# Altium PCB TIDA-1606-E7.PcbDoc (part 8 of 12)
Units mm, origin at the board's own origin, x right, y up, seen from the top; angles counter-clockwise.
Board outline 270 x 345 mm, 4 copper layers (Top Layer, Signal Layer 1, Signal Layer 2, Bottom Layer), stack 2.326 mm thick; 1282 components, 576 nets, 3628 pads, 4132 vias.
Unrouted connection lines stored in the file: 1719.
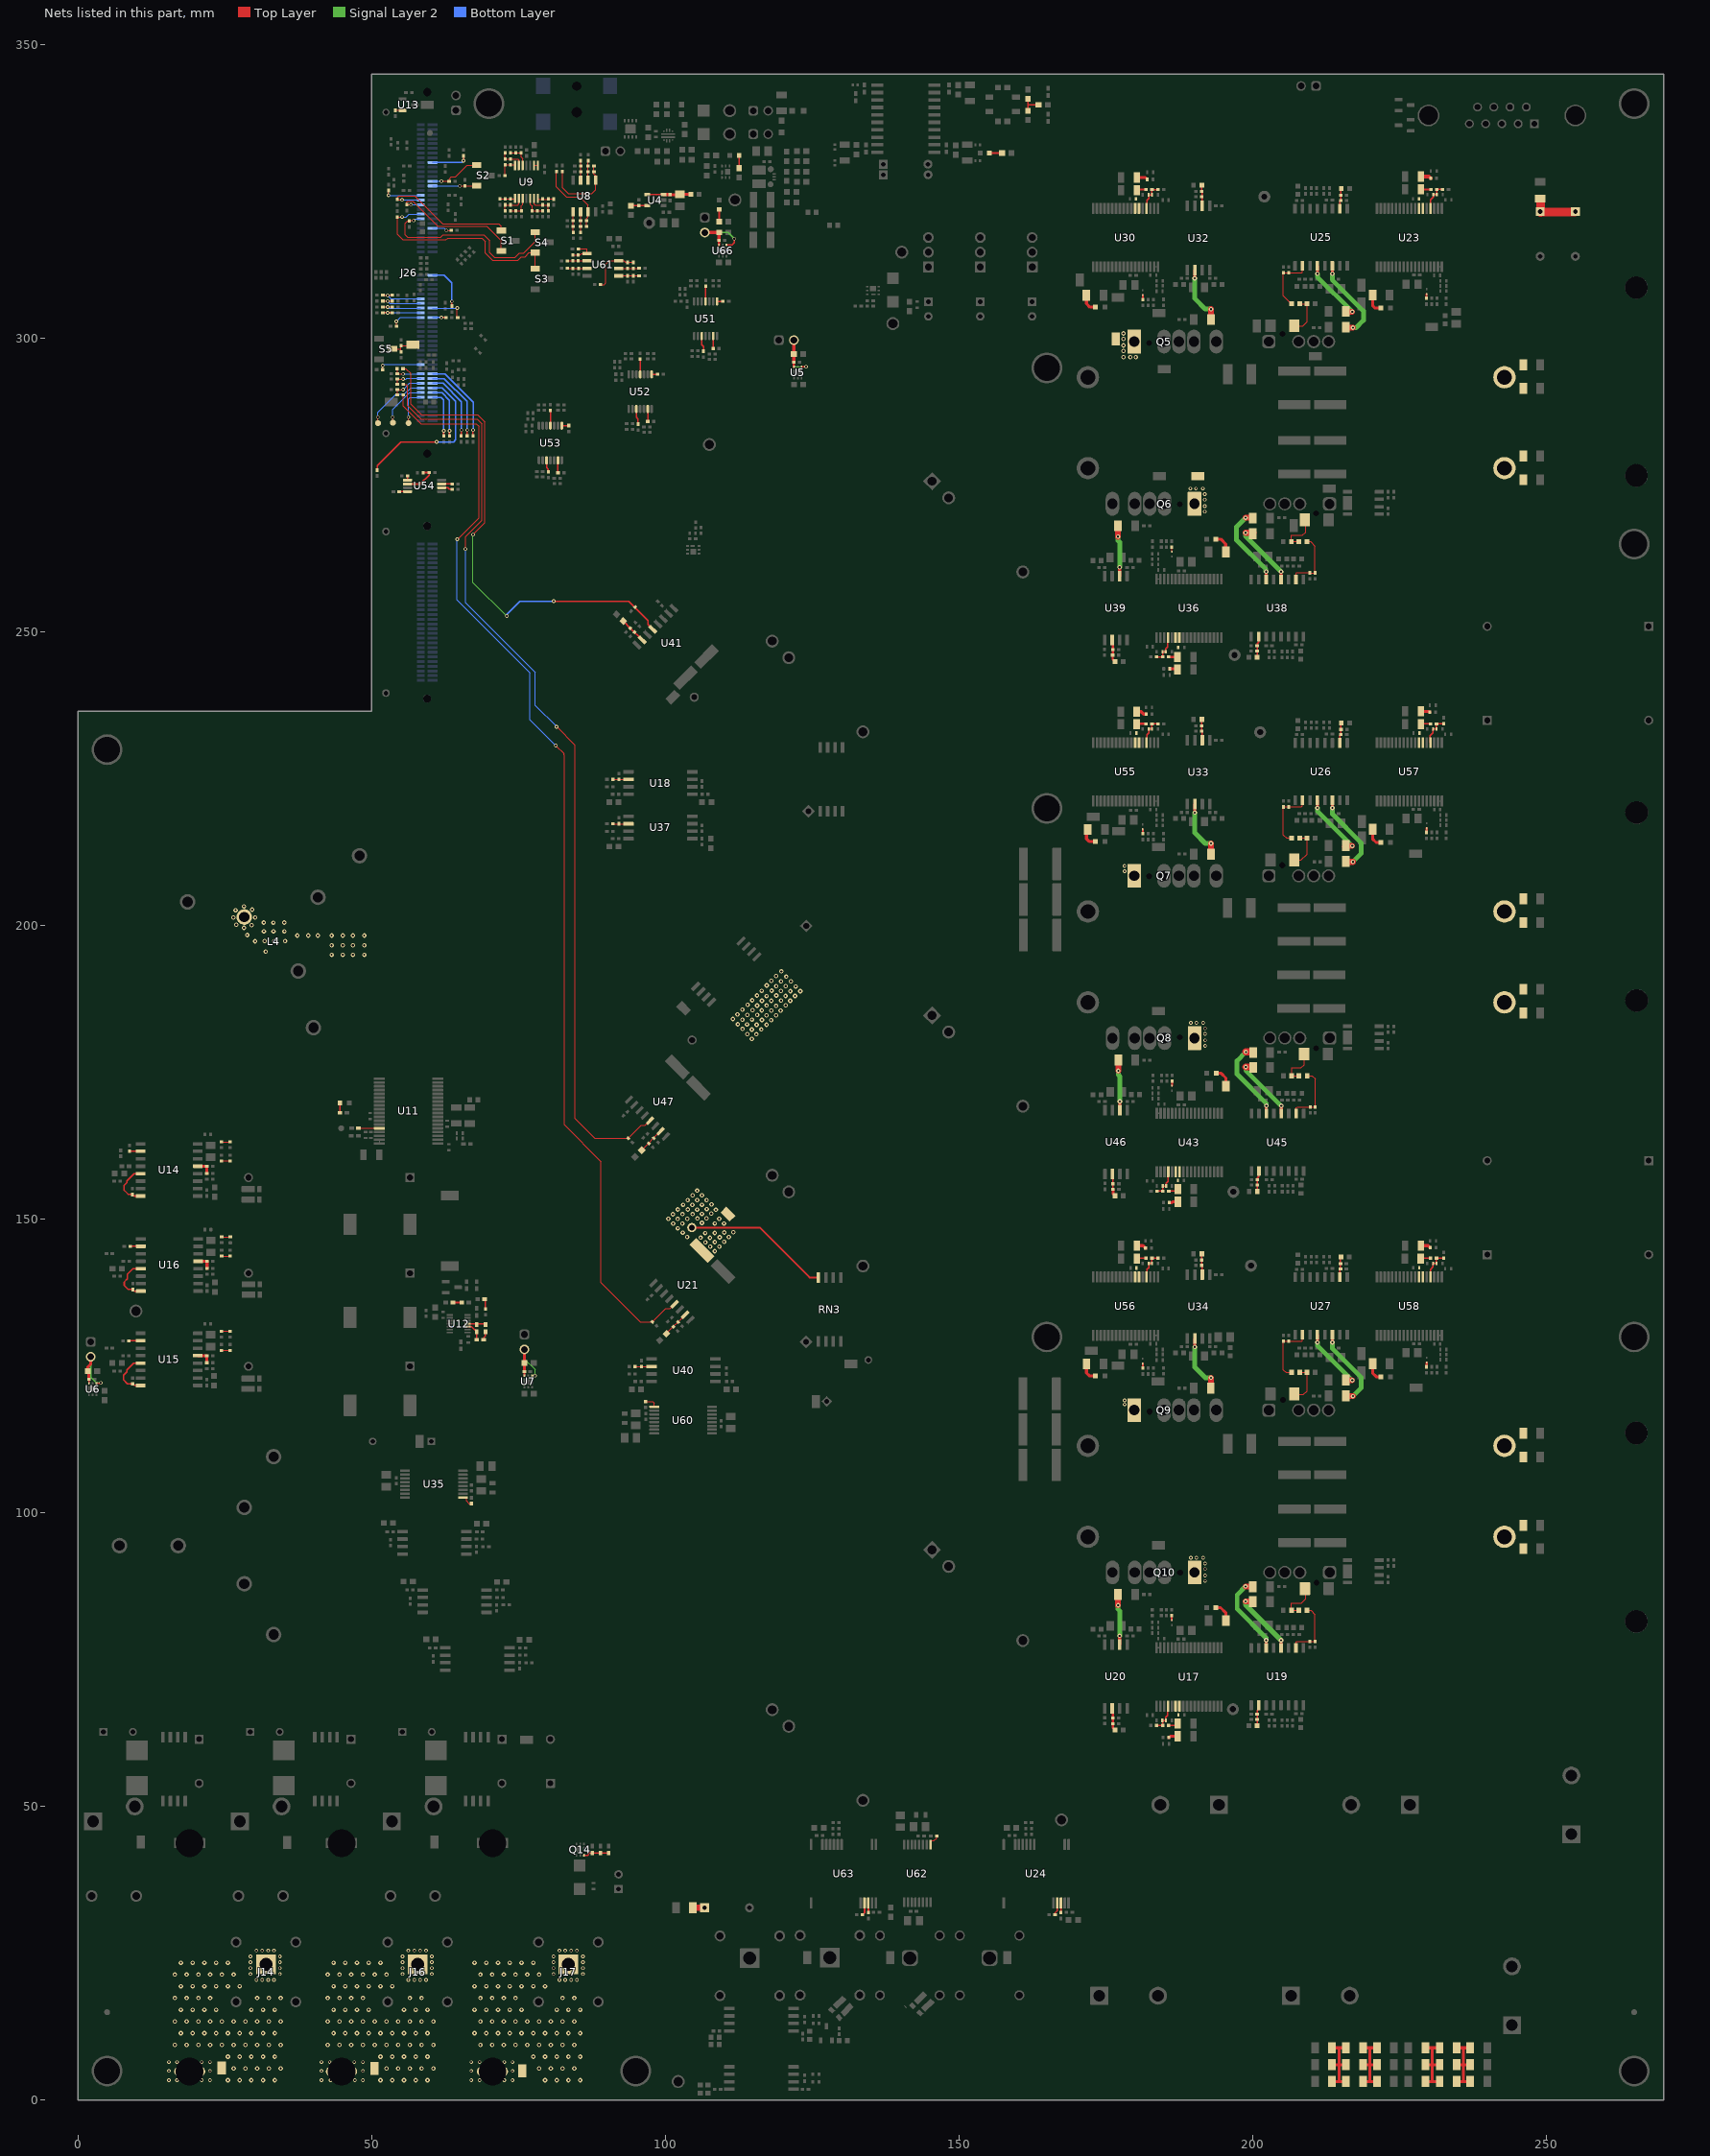
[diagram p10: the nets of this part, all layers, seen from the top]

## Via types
v1: diameter 0.762, hole 0.356, Top Layer to Bottom Layer, tented both sides, 2905 vias
v2: diameter 0.61, hole 0.356, Top Layer to Bottom Layer, tented both sides, 1212 vias
v3: diameter 0.864, hole 0.406, Top Layer to Bottom Layer, tented both sides, 15 vias

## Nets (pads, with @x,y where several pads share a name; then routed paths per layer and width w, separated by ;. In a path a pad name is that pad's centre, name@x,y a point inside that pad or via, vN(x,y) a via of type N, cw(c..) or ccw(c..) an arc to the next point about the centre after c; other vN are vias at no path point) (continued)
I_SN_L3-: C70.2 L4.AIII RN3.4 TP37.1 U21.2 | length 25.1
  Top Layer w0.305: C70.2@104.548,148.612 116.088,148.612 124.6,140.1 RN3.4@126.1,140.1
  other v1: 108.455,144.596 107.684,145.358 109.231,145.376 106.861,146.096 108.46,146.139 110.055,146.196 107.637,146.876 106.055,146.896 109.284,146.958 103.768,146.996 110.855,147.01 106.831,147.676 108.461,147.696 102.996,147.758 110.084,147.773 111.618,147.81 102.173,148.496 102.95,149.276 101.368,149.296 108.455,149.31 110.023,149.31 106.268,149.396 102.144,150.076 100.568,150.096 103.773,150.096 109.218,150.11 105.496,150.158 107.044,150.176 101.344,150.876 102.968,150.896 104.673,150.896 106.273,150.939 107.868,150.996 108.642,151.635 105.45,151.676 102.168,151.696 103.868,151.696 107.096,151.758 104.644,152.476 103.068,152.496 106.273,152.496 107.896,152.558 103.844,153.276 105.468,153.296 107.073,153.296 104.668,154.096 106.268,154.096 105.468,154.896 114.783,180.752 113.983,181.552 115.559,181.533 114.759,182.333 116.383,182.352 113.186,182.43 115.583,183.152 117.283,183.152 113.962,183.211 112.386,183.23 118.059,183.933 116.483,183.952 113.162,184.011 114.786,184.03 111.553,184.13 117.259,184.733 118.883,184.752 113.986,184.83 115.686,184.83 112.329,184.911 118.083,185.552 119.683,185.552 116.462,185.611 114.886,185.63 113.153,185.73 118.883,186.352 115.662,186.411 117.286,186.43 120.532,186.461 114.053,186.53 116.486,187.23 118.086,187.23 121.308,187.241 119.732,187.261 114.829,187.311 117.286,188.03 120.508,188.041 122.132,188.061 115.653,188.13 118.935,188.139 121.332,188.861 123.032,188.861 116.453,188.93 118.135,188.939 119.711,188.919 122.232,189.661 118.911,189.719 120.535,189.739 117.302,189.839 119.735,190.539 121.435,190.539 118.078,190.619 120.635,191.339 118.902,191.439 119.802,192.239 43.221,195.054 45.131,195.054 46.851,195.054 48.782,195.054 32,195.605 43.221,196.657 45.131,196.657 46.851,196.657 48.782,196.657 30.2,197.356 33.444,197.401 31.813,197.409 35.299,197.409 37.385,198.342 39.241,198.342 40.872,198.342 43.221,198.342 45.131,198.342 46.851,198.342 48.782,198.342 28.845,198.422 33.331,199.052 31.7,199.06 35.186,199.06 28.303,199.656 29.6,200.1 27,200.186 31.669,200.54 33.3,200.532 35.155,200.54 26.503,201.4 30.2,201.4 26.881,202.65 29.677,202.761 28.303,203.3
ID_A: J26.53 R436.1 R441.2 | length 7.5
  Top Layer w0.203: R436.1@51.943,307.385 R441.2@53.524,307.385
  Bottom Layer w0.203: v2(52.753,307.368) 53.336,306.785 J26.53@58.402,306.785
ID_B: J26.51 R438.1 R442.2 | length 7.6
  Top Layer w0.203: R438.1@51.943,306.385 v2(52.753,306.385) R442.2@53.524,306.385
  Bottom Layer w0.203: v2@52.517,306.385 52.532,306.4 v2@52.649,306.282 ; v2(52.753,306.385) 53.153,305.985 J26.51@58.402,305.985
ID_C: J26.49 R439.1 R443.2 | length 7.6
  Top Layer w0.203: R439.1@51.943,305.385 52.738,305.385 v2(52.753,305.371) 53.509,305.371 R443.2@53.524,305.385
  Bottom Layer w0.203: v2@52.642,305.26 52.717,305.185 v2@52.938,305.185 ; v2(52.753,305.371) v2@52.938,305.185 ; J26.49@58.402,305.185 v2@52.938,305.185
ID_D: J26.47 R440.1 R444.2 | length 7.2
  Top Layer w0.229: R440.1@51.943,304.385 v2(52.753,304.385) R444.2@53.524,304.385
  Bottom Layer w0.203: v2(52.753,304.385) J26.47@58.402,304.385
IN+_BOT_L1: C186.1 R196.1 R197.2 U25.10 | length 3.5
  Top Layer w0.229: U25.10@214.88,322.108 214.88,323.362 C186.1@215.029,323.511 R197.2@215.029,324.397 215.029,325.418 R196.1@215.129,325.518
IN+_BOT_L2: C199.1 R210.1 R212.2 U26.10 | length 3.5
  Top Layer w0.229: U26.10@214.882,231.14 214.882,232.367 C199.1@215.058,232.542 R210.1@215.058,234.477
  Top Layer w0.5: R210.1@215.058,234.477 R210.1@215.131,234.55
IN+_BOT_L3: C212.1 R211.1 R227.2 U27.10 | length 3.5
  Top Layer w0.229: U27.10@214.882,140.144 214.882,141.434 C212.1@214.995,141.547 R227.2@214.995,142.433 214.995,143.5 R211.1@215.095,143.6
IN+_TOP_L1: C290.1 R246.1 R288.2 U38.10 | length 3.6
  Top Layer w0.229: R246.1@200.698,245.739 200.798,245.839 R288.2@200.798,246.798 C290.1@200.798,247.719 200.798,248.067 201.068,248.337 U38.10@201.068,249.222
IN+_TOP_L2: C333.1 R264.1 R327.2 U45.10 | length 3.6
  Top Layer w0.229: R264.1@200.839,154.773 R327.2@200.839,155.832 C333.1@200.839,156.753 200.839,157.055 201.109,157.325 U45.10@201.109,158.256
IN+_TOP_L3: C146.1 R157.1 R158.2 U19.10 | length 3.6
  Top Layer w0.254: R157.1@200.8,63.778 R158.2@200.8,64.836 C146.1@200.8,65.758 200.8,66.358 201.07,66.628 U19.10@201.07,67.261
L1_MID_DRAIN: Q5.1 Q6.1 TP30.1 TP31.1
  other v1: 178.049,296.822 179.206,296.822 180.147,296.822 178.049,297.877 178.049,298.818 178.043,299.917 178.043,300.858
  other v2: 191.882,270.521 191.882,271.462 191.876,272.561 191.876,273.502 189.454,274.458 190.395,274.458 191.552,274.458
L2_MID_DRAIN: Q7.1 Q8.1
  other v2: 191.947,179.555 191.947,180.496 191.94,181.595 191.94,182.536 189.519,183.492 190.46,183.492 191.616,183.492 178.251,209.289 178.227,210.173
L3_MID_DRAIN: Q9.1 Q10.1
  other v2: 191.933,88.439 191.933,89.38 191.926,90.479 191.926,91.42 189.505,92.375 190.446,92.375 191.602,92.375 178.251,118.506 178.251,119.167
LMK_1G: R461.1 U54.2 | length 1.9
  Top Layer w0.229: U54.2@61.951,274.578 63.025,274.578 63.254,274.348 R461.1@63.737,274.348
LMK_VDD: C393.2 R287.2 U54.6 | length 5.7
  Top Layer w0.305: U54.6@56.151,275.228 58.317,275.228 59.837,276.748 C393.2@59.837,277.148 R287.2@58.837,277.148
LO_MAG_VIN_L1: C172.1 C173.1 C174.1 FB10.2 R188.2 U23.6 U23.7 | length 3.6
  Top Layer w0.305: C172.1@228.732,325.054 229.083,325.405 R188.2@230.388,325.405
  Top Layer w0.6: C173.1@228.691,327.585 230.097,327.585 FB10.2@230.378,327.304
LO_MAG_VIN_L2: C413.1 C414.1 C415.1 FB11.2 R529.2 U57.6 U57.7 | length 3.4
  Top Layer w0.229: C414.1@228.675,234.074 229.001,234.4 R529.2@230.34,234.4
  Top Layer w0.5: C413.1@228.684,236.529 230.06,236.529 FB11.2@230.216,236.372
LO_MAG_VIN_L3: C421.1 C422.1 C423.1 FB12.2 R537.2 U58.6 U58.7 | length 3.5
  Top Layer w0.229: C421.1@228.675,143.078 229.001,143.405 R537.2@230.34,143.405
  Top Layer w0.5: C422.1@228.683,145.529 229.933,145.529 FB12.2@230.257,145.205
MCU_REF1: J4.1 J5.1 L9.2 | length 8
  Top Layer w1.5: L9.2@249.05,323.655 249.05,321.47 249.1,321.52 J4.1@254.868,321.52
MCU_REF2: J6.1 L6.2 | length 2
  Top Layer w1: L6.2@104.733,32.8 106.726,32.8 J6.1@106.738,32.788
MID_MAG_EN_L2: C402.1 R280.1 R342.2 R361.2 U55.4 | length 4.9
  Top Layer w0.229: U55.4@181.98,231.197 182.041,231.258 182.041,232.542 182.346,232.847 C402.1@182.346,233.5 R342.2@182.901,233.5 182.901,234.396 R280.1@182.904,234.396 ; R280.1@182.899,234.4 R361.2@183.924,234.4
MID_MAG_EN_L3: C410.1 R363.2 R509.1 R512.2 U56.4 | length 4.9
  Top Layer w0.229: U56.4@181.98,140.201 182.041,140.262 182.041,141.484 182.346,141.789 C410.1@182.346,142.505 182.896,142.505 R512.2@182.901,142.5 182.901,143.403 R509.1@182.899,143.405 R363.2@183.924,143.405
MID_MAG_VIN_L1: C232.1 C233.1 C234.1 FB13.2 R250.2 U30.6 U30.7 | length 3.5
  Top Layer w0.305: C232.1@180.389,325.042 180.715,325.368 R250.2@181.897,325.368
  Top Layer w0.5: C233.1@180.344,327.406 181.792,327.406 FB13.2@182.098,327.1
MID_MAG_VIN_L2: C397.1 C398.1 C399.1 FB14.2 R280.2 U55.6 U55.7 | length 3.4
  Top Layer w0.4: C397.1@180.391,234.074 180.717,234.4 R280.2@181.899,234.4
  Top Layer w0.5: C398.1@180.306,236.451 181.071,236.451 181.479,236.042 FB14.2@181.904,236.042
MID_MAG_VIN_L3: C405.1 C406.1 C407.1 FB15.2 R509.2 U56.6 U56.7 | length 3.3
  Top Layer w0.229: C405.1@180.391,143.078 180.717,143.405 R509.2@181.899,143.405
  Top Layer w0.5: C406.1@180.332,145.529 181.378,145.529 FB15.2@181.797,145.11
MP1: MP1.1 R117.2 R120.2
MP2: MP2.2 R118.2 R121.2
MP3: MP3.1 R119.2 R122.2
MP4: MP4.2 R123.2 R126.2
MP5: MP5.2 R124.2 R127.2
MP6: MP6.1 R125.2 R128.2
NetC15_1: C15.1 C16.1 R35.1 U4.3 U4.4 | length 7.5
  Top Layer w0.305: U4.4@96.966,324.52 U4.3@99.716,324.52 ; C15.1@100.825,324.52 C15.1@100.845,324.5 ; C16.1@102.482,324.5 C16.1@102.54,324.558
  Top Layer w0.508: U4.3@99.716,324.52 C15.1@100.825,324.52 ; C15.1@100.845,324.5 C16.1@102.482,324.5 ; C16.1@102.54,324.558 R35.1@104.39,324.558
NetC17_1: C17.1 C18.1 J10.2 U5.4 U5.6 | length 11.7
  Top Layer w0.254: U5.4@123.238,295.193 v2(123.993,295.193)
  Top Layer w0.381: C18.1@121.92,295.977 121.938,295.959 U5.6@121.938,295.193
  Top Layer w0.508: C18.1@121.92,295.977 C17.1@121.92,297.377 J10.2@121.92,299.72
  Signal Layer 2 w0.203: J10.2@121.92,299.72 121.92,295.518 122.245,295.193 v2(123.993,295.193)
NetC22_1: C22.1 C23.1 J11.2 U6.4 U6.6 | length 11.2
  Top Layer w0.254: U6.6@1.9,122.087 C23.1@1.9,122.8 ; U6.4@3.2,122.087 3.866,122.087 v2(3.933,122.154)
  Top Layer w0.508: C23.1@1.9,122.8 1.9,123.961 C22.1@1.7,124.161 1.7,124.873 2.2,125.373 J11.2@2.2,126.6
  Signal Layer 2 w0.254: J11.2@2.2,126.6 2.2,123.133 3.178,122.154 v2(3.933,122.154)
NetC25_1: C25.1 C26.1 J12.2 U7.4 U7.6 | length 10.3
  Top Layer w0.203: U7.4@77.34,123.376 v2(77.856,123.376)
  Top Layer w0.381: U7.6@76.04,123.376 C26.1@76.04,124.108
  Top Layer w0.508: C26.1@76.04,124.108 C25.1@76.04,125.532 J12.2@76.04,127.872
  Signal Layer 2 w0.203: J12.2@76.04,127.872 76.04,126.268 77.856,124.452 v2(77.856,123.376)
NetC32_2: C32.2 R19.1 R22.1 U61.3 | length 3.3
  Top Layer w0.203: R22.1@83.37,311.962 R19.1@84.27,311.962 84.278,311.954 U61.3@86.702,311.954
NetC35_2: C35.2 U24.4 | length 1.6
  Top Layer w0.254: C35.2@167.401,31.956 U24.4@167.401,33.6
NetC62_1: C62.1 R65.1 U18.6 | length 2.6
  Top Layer w0.203: R65.1@91.1,224.939 C62.1@92.12,224.939 U18.6@93.75,224.939
NetC88_1: C88.1 R66.2 | length 1.6
  Top Layer w0.203: C88.1@69.275,136.432 C88.1@69.418,136.289
  Top Layer w0.254: R66.2@69.418,134.863 C88.1@69.418,136.289
NetC91_1: C91.1 R67.1 | length 1.5
  Top Layer w0.381: R67.1@63.849,135.846 C91.1@65.381,135.846
NetC98_1: C98.1 Q14.3 R113.2 R115.2 | length 4.4
  Top Layer w0.229: Q14.3@86.202,41.725 86.766,41.725 87.141,42.1 C98.1@87.627,42.1 R115.2@89.014,42.1 R113.2@90.4,42.1
NetC99_1: C99.1 R72.2 U12.10 | length 3.3
  Top Layer w0.254: U12.10@66.365,131.738 67.063,131.738 C99.1@67.913,130.888 R72.2@67.913,129.515
NetC99_2: C99.2 C101.2 U12.11 | length 3.1
  Top Layer w0.254: U12.11@66.365,132.238 69.268,132.238 C101.2@69.418,132.088
NetC100_2: C100.2 R306.1 R309.1 U9.5 | length 4.1
  Top Layer w0.203: R309.1@73.674,331.6 73.679,331.605 R306.1@74.586,331.605 C100.2@75.51,331.605 ; C100.2@75.535,331.605 75.535,330.892 75.752,330.675 U9.5@75.752,329.468
NetC101_1: C101.1 R72.1 | length 1.5
  Top Layer w0.254: R72.1@69.113,129.515 69.113,129.868 69.418,130.173 C101.1@69.418,130.888
NetC107_2: C107.2 U14.13 U14.16 | length 7.8
  Top Layer w0.254: U14.16@10.691,153.98 9.59,153.98 C107.2@9.331,154.239 9.278,154.292 8.573,154.292 7.9,154.965 7.9,155.809 8.373,156.282 8.373,156.573 9.59,157.79 U14.13@10.691,157.79
NetC109_1: C109.1 C111.1 U14.5 | length 2.7
  Top Layer w0.5: U14.5@20.441,159.06 C111.1@21.965,159.06 C109.1@21.965,157.856
NetC116_2: C116.2 U15.13 U15.16 | length 8.1
  Top Layer w0.254: U15.16@10.691,121.722 9.612,121.722 C116.2@9.342,121.992 8.462,121.992 7.772,122.682 7.772,123.469 8.354,124.051 8.354,124.384 9.502,125.532 U15.13@10.691,125.532
NetC118_1: C118.1 C120.1 U15.5 | length 2.7
  Top Layer w0.5: U15.5@20.441,126.802 C120.1@21.965,126.802 C118.1@21.965,125.598
NetC125_2: C125.2 U16.13 U16.16 | length 8
  Top Layer w0.254: U16.16@10.733,137.795 9.633,137.795 C125.2@9.363,138.065 8.599,138.065 7.911,138.753 7.911,139.35 8.454,139.893 8.454,140.671 9.388,141.605 U16.13@10.733,141.605
NetC127_1: C127.1 C129.1 U16.5 | length 2.7
  Top Layer w0.5: U16.5@20.483,142.875 C129.1@22.007,142.875 C127.1@22.007,141.671
NetC132_1: C132.1 C133.1 C134.1 FB21.2 R153.2 U17.6 U17.7 | length 3.2
  Top Layer w0.229: R153.2@185.719,63.836 186.955,63.836 C133.1@187.268,64.149
  Top Layer w0.5: FB21.2@185.797,61.788 186.008,62 C132.1@187.267,62
NetC143_1: C143.1 R152.2 R153.1 R364.2 U17.4 | length 5
  Top Layer w0.229: R364.2@183.703,63.836 R153.1@184.719,63.836 184.719,64.685 C143.1@185.26,64.685 185.26,65.205 185.57,65.515 185.57,67.068 U17.4@185.626,67.124
NetC156_1: C156.1 R166.1 R169.2 U19.2 | length 10.6
  Top Layer w0.203: U19.2@207.42,77.011 207.42,78.067 207.514,78.161 209.773,78.161 C156.1@209.8,78.134 R169.2@210.666,78.134 210.666,82.746 209.959,83.452 R166.1@209.284,83.452
NetC162_1: C162.1 R174.1 R175.1 U20.2 | length 3.9
  Top Layer w0.4: U20.2@176.121,66.707 176.221,66.607 C162.1@176.221,65.073 R175.1@176.221,64.145 176.221,63.421 R174.1@176.595,63.047
NetC167_2: C167.2 R311.1 R313.2 U9.6 | length 4.4
  Top Layer w0.203: R311.1@72.761,331.6 72.776,331.585 72.776,330.56 72.784,330.568 C167.2@73.676,330.568 73.676,330.593 74.914,330.593 75.102,330.405 U9.6@75.102,329.468
NetC169_2: C169.2 R345.1 R346.1 U9.10 | length 4.1
  Top Layer w0.203: R346.1@73.674,321.753 R345.1@74.6,321.753 C169.2@75.535,321.753 75.535,322.605 75.752,322.822 U9.10@75.752,323.868
NetC175_1: C175.1 R25.1 R28.1 U61.2 | length 3.3
  Top Layer w0.203: R25.1@83.37,313.226 83.372,313.224 R28.1@84.27,313.224 C175.1@85.226,313.224 U61.2@86.702,313.224
NetC183_1: C183.1 R188.1 R193.2 R446.2 U23.4 | length 5
  Top Layer w0.229: U23.4@230.356,322.214 230.356,323.635 230.81,324.089 C183.1@230.81,324.505 R193.2@231.388,324.505 R188.1@231.388,325.405 R446.2@232.381,325.405
NetC196_1: C196.1 R205.1 R208.2 U25.2 | length 10.2
  Top Layer w0.203: R205.1@206.666,305.914 205.284,307.296 R208.2@205.284,311.208 C196.1@206.152,311.208 208.462,311.208 208.53,311.276 U25.2@208.53,312.358
NetC209_1: C209.1 R220.1 R223.2 U26.2 | length 10.7
  Top Layer w0.203: R220.1@206.668,214.945 205.803,214.945 205.286,215.462 R223.2@205.286,220.24 C209.1@206.154,220.24 208.37,220.24 208.532,220.402 U26.2@208.532,221.39
NetC223_1: C223.1 R234.1 R239.1 U8.3 | length 3.3
  Top Layer w0.203: U8.3@85.617,326.954 85.617,330.278 R239.1@85.625,330.286
NetC228_1: C228.1 R236.1 R245.2 U27.2 | length 10.8
  Top Layer w0.203: R236.1@206.668,123.95 205.714,123.95 205.286,124.378 R245.2@205.286,129.244 C228.1@206.154,129.244 208.437,129.244 208.532,129.34 U27.2@208.532,130.394
NetC230_1: C230.1 R241.1 R244.2 U8.2 | length 3.3
  Top Layer w0.203: U8.2@86.887,326.954 C230.1@86.887,328.43 R244.2@86.887,329.386 86.887,330.284 R241.1@86.889,330.286
NetC243_1: C243.1 R250.1 R255.2 R447.2 U30.4 | length 4.9
  Top Layer w0.229: U30.4@181.978,322.165 182.039,322.226 182.039,323.539 182.344,323.844 C243.1@182.344,324.468 R255.2@182.899,324.468 182.899,325.366 R250.1@182.897,325.368 R447.2@183.922,325.368
NetC249_1: C249.1 R224.1 R261.1 U32.2 | length 3.6
  Top Layer w0.229: R224.1@191.375,326.11 R261.1@191.375,325.039 191.465,324.949 U32.2@191.465,322.568
NetC256_1: C256.1 R226.1 R265.1 U33.2 | length 3.6
  Top Layer w0.229: R226.1@191.377,235.142 R265.1@191.377,234.071 C256.1@191.377,233.174 191.467,233.084 U33.2@191.467,231.6
NetC263_1: C263.1 R242.1 R269.1 U34.2 | length 3.6
  Top Layer w0.229: R242.1@191.377,144.147 C263.1@191.377,143.076 R269.1@191.377,142.178 191.467,142.088 U34.2@191.467,140.605
NetC272_1: C272.1 R270.1 R272.2 U8.5 | length 3.5
  Top Layer w0.203: R272.2@84.347,318.089 R270.1@84.347,319.086 C272.1@84.347,320.059 U8.5@84.347,321.554
NetC275_1: C275.1 R274.2 R276.1 U8.6 | length 3.5
  Top Layer w0.203: R274.2@85.614,318.089 R276.1@85.614,319.086 C275.1@85.614,320.059 85.617,320.062 U8.6@85.617,321.554
NetC276_1: C276.1 C277.1 C278.1 FB22.2 R279.2 U36.6 U36.7 | length 3.1
  Top Layer w0.4: R279.2@185.717,245.798 186.953,245.798 C276.1@187.266,246.111
  Top Layer w0.5: FB22.2@185.903,243.764 187.107,243.764 C277.1@187.248,243.623
NetC287_1: C287.1 R279.1 R282.2 R448.2 U36.4 | length 5
  Top Layer w0.229: R448.2@183.701,245.798 R279.1@184.717,245.798 184.717,246.646 C287.1@185.258,246.646 185.258,247.16 185.568,247.47 185.568,248.643 185.624,248.699 U36.4@185.624,249.085
NetC306_1: C306.1 R260.1 R305.1 U39.2 | length 3.9
  Top Layer w0.4: U39.2@176.119,248.668 176.219,248.568 C306.1@176.219,247.035 R305.1@176.219,246.106 ; R305.1@176.206,246.093 176.206,245.379 R260.1@176.585,245
NetC313_2: C313.2 R348.1 R349.2 U9.9 | length 4.4
  Top Layer w0.203: R348.1@72.761,321.753 72.761,322.742 72.759,322.743 74.919,322.743 75.102,322.927 U9.9@75.102,323.868
NetC314_2: C314.2 R17.2 U4.5 | length 2.8
  Top Layer w0.25: R17.2@94.16,322.62 C314.2@95.532,322.62 U4.5@96.966,322.62
NetC316_2: C316.2 R176.1 R179.1 U9.12 | length 4.1
  Top Layer w0.203: U9.12@77.052,323.868 77.052,322.836 77.362,322.526 C316.2@77.362,321.753 R176.1@78.251,321.753 R179.1@79.187,321.753
NetC319_1: C319.1 C320.1 C321.1 FB23.2 R316.2 U43.6 U43.7 | length 3.2
  Top Layer w0.229: R316.2@185.758,154.832 186.994,154.832 C319.1@187.307,155.145
  Top Layer w0.5: FB23.2@185.828,152.857 186.28,152.857 186.42,152.997 187.308,152.997 C320.1@187.31,153
NetC330_1: C330.1 R316.1 R321.2 R450.2 U43.4 | length 5
  Top Layer w0.229: R450.2@183.742,154.832 R316.1@184.758,154.832 184.758,155.68 C330.1@185.3,155.68 185.3,156.168 185.61,156.478 185.61,158.063 U43.4@185.666,158.119
NetC335_2: C335.2 R181.1 R184.2 U9.13 | length 4.4
  Top Layer w0.203: U9.13@77.702,323.868 77.702,322.885 77.859,322.729 79.187,322.729 79.188,322.73 80.111,322.73 R181.1@80.111,321.753
NetC343_1: C343.1 R335.1 R338.2 U45.2 | length 10.7
  Top Layer w0.203: U45.2@207.459,168.006 207.459,169.032 207.584,169.156 209.815,169.156 C343.1@209.839,169.132 R338.2@210.705,169.132 210.705,173.925 210.18,174.45 R335.1@209.323,174.45
NetC349_1: C349.1 R268.1 R337.1 U46.2 | length 3.9
  Top Layer w0.229: U46.2@176.169,157.71 176.261,157.618 C349.1@176.261,156.069 R337.1@176.261,155.14
  Top Layer w0.5: R337.1@176.261,155.14 176.261,154.4 R268.1@176.627,154.034
NetC351_1: C351.1 R70.1 U37.6 | length 2.7
  Top Layer w0.203: R70.1@91.1,217.374 C351.1@92.12,217.374 U37.6@93.75,217.374
NetC359_1: C359.1 R75.1 U40.6 | length 2.8
  Top Layer w0.203: R75.1@94.889,124.952 C359.1@95.989,124.952 U40.6@97.693,124.952
NetC378_2: C378.2 R385.1 R386.2 | length 3.8
  Top Layer w0.229: R386.2@161.798,338.8 161.798,339.806 ; R385.1@161.798,340.812 161.798,339.806 ; C378.2@163.576,339.8 161.804,339.8 161.798,339.806
NetC385_1: C385.1 R374.1 S5.2 TP9.1 | length 4.6
  Top Layer w0.203: S5.2@53.602,298.237 54.991,298.237 55.019,298.265 ; C385.1@55.019,297.74 55.019,298.265 ; TP9.1@57.067,298.965 56.891,298.789 R374.1@55.019,298.789 55.019,298.265
NetC418_1: C418.1 R351.2 R529.1 R532.2 U57.4 | length 5.3
  Top Layer w0.229: U57.4@230.252,231.14 230.252,232.341 230.762,232.851 C418.1@230.762,233.5 R532.2@231.34,233.5 R529.1@231.34,234.4 R351.2@232.548,234.4
NetC425_1: C425.1 R183.2 R185.1 U21.9 | length 4.6
  Top Layer w0.203: R183.2@100.214,130.543 103.42,133.748 U21.9@103.42,133.776
NetC426_1: C426.1 R353.2 R537.1 R540.2 U58.4 | length 5.2
  Top Layer w0.229: U58.4@230.309,140.201 230.309,141.469 230.762,141.921 C426.1@230.762,142.505 R540.2@231.34,142.505 R537.1@231.34,143.405 R353.2@232.548,143.405
NetC429_1: C429.1 R312.2 R314.1 U41.9 | length 4.6
  Top Layer w0.229: R312.2@92.879,251.9 92.879,251.878 R314.1@94.058,250.7 96.063,248.695 U41.9@96.112,248.695
NetC430_1: C430.1 R344.1 R352.2 U47.9 | length 4.6
  Top Layer w0.203: R352.2@96.028,161.785 96.028,161.812 U47.9@99.234,165.018
NetC444_2: C444.2 R29.1 R32.1 U61.5 | length 3.5
  Top Layer w0.203: U61.5@92.102,310.684 C444.2@93.597,310.684 R29.1@94.57,310.684 95.567,310.684 R32.1@95.57,310.687
NetC452_1: C452.1 C483.1 J31.2 U66.4 U66.6 | length 12.1
  Top Layer w0.254: U66.4@110.467,315.958 111.409,315.958 111.798,316.346 v2(111.798,316.998)
  Top Layer w0.381: U66.6@109.167,315.958 C483.1@109.167,316.7
  Top Layer w0.508: J31.2@106.767,318.06 109.167,318.06 C483.1@109.167,316.7
  Signal Layer 2 w0.254: J31.2@106.767,318.06 110.736,318.06 v2(111.798,316.998)
NetC454_2: C454.2 U63.4 | length 1.6
  Top Layer w0.305: C454.2@134.599,31.956 U63.4@134.599,33.6
NetC455_1: C455.1 R34.1 R37.1 U61.6 | length 3.5
  Top Layer w0.203: U61.6@92.102,311.954 95.562,311.954 R34.1@95.57,311.962
NetD1_1: D1.1 R7.2 | length 2.2
  Top Layer w0.305: R7.2@112.602,329.02 D1.1@112.602,331.17
NetD3_1: D3.1 R15.2 | length 2.1
  Top Layer w0.254: R15.2@109.193,319.902 R15.2@109.209,319.885
  Top Layer w0.305: R15.2@109.193,319.902 D3.1@109.193,321.985
NetD4_1: D4.1 R61.2 | length 1.7
  Top Layer w0.305: R61.2@44.635,168.163 D4.1@44.635,169.816
NetD7_2: D7.2 R149.1 | length 0.8
  Top Layer w0.305: D7.2@186.276,81.754 R149.1@186.276,82.534
NetD8_2: D8.2 R163.1 R166.2 | length 7
  Top Layer w0.203: R166.2@207.884,83.452 R163.1@206.644,83.452 206.644,84.684 208.357,84.684 209.062,85.389 D8.2@209.062,87.21
NetD10_2: D10.2 R202.1 R205.2 | length 7
  Top Layer w0.203: D10.2@206.888,302.157 208.619,302.157 209.306,302.844 R202.1@209.306,305.914 R205.2@208.066,305.914
NetD11_2: D11.2 R217.1 R220.2 | length 6.8
  Top Layer w0.203: D11.2@206.89,211.188 208.266,211.188 209.306,212.228 209.306,214.943 R217.1@209.308,214.945 R220.2@208.068,214.945
NetD12_2: D12.2 R232.1 R236.2 | length 7.1
  Top Layer w0.203: D12.2@206.89,120.193 208.693,120.193 209.308,120.808 R232.1@209.308,123.95 R236.2@208.068,123.95
NetD14_2: D14.2 R277.1 | length 0.8
  Top Layer w0.203: D14.2@186.274,263.718 R277.1@186.274,264.498
NetD15_2: D15.2 R293.1 R296.2 | length 7.1
  Top Layer w0.203: R296.2@207.882,265.416 R293.1@206.642,265.416 206.644,265.418 206.644,266.502 208.527,266.502 209.06,267.036 D15.2@209.06,269.173
NetD16_2: D16.2 R284.1 | length 0.8
  Top Layer w0.35: D16.2@186.316,172.752 R284.1@186.316,173.532
NetD17_2: D17.2 R332.1 R335.2 | length 6.8
  Top Layer w0.203: R335.2@207.923,174.45 R332.1@206.683,174.45 206.683,175.817 208.28,175.817 208.802,176.339 D17.2@208.802,178.151
NetD18_1: D18.1 R382.2 | length 2.1
  Top Layer w0.305: D18.1@155.241,331.605 157.36,331.605 R382.2@157.379,331.585
NetD19_2: D19.2 R186.1 | length 0.7
  Top Layer w0.35: R186.1@229.657,306.873 D19.2@229.657,307.586
  Top Layer w0.4: R186.1@229.657,306.873 R186.1@229.664,306.866
NetD20_2: D20.2 R535.1 | length 0.7
  Top Layer w0.35: R535.1@229.666,215.898 D20.2@229.666,216.611
NetD21_2: D21.2 R557.1 | length 0.7
  Top Layer w0.35: R557.1@229.666,124.902 D21.2@229.666,125.616
NetD22_1: D22.1 R560.2 | length 3.4
  Top Layer w0.5: R560.2@220.448,307.391 220.448,305.625 220.905,305.168 D22.1@221.898,305.168
NetD23_1: D23.1 R561.2 | length 3.3
  Top Layer w0.5: R561.2@220.45,216.423 220.45,214.8 221.05,214.2 D23.1@221.9,214.2
NetD24_1: D24.1 R562.2 | length 3.3
  Top Layer w0.5: R562.2@220.45,125.428 220.45,123.85 221.095,123.205 D24.1@221.9,123.205
NetD25_2: D25.2 R507.1 | length 0.7
  Top Layer w0.35: R507.1@181.328,306.646 D25.2@181.328,307.391
NetD26_2: D26.2 R565.1 | length 0.7
  Top Layer w0.35: R565.1@181.33,215.678 D26.2@181.33,216.423
NetD27_2: D27.2 R567.1 | length 0.7
  Top Layer w0.35: R567.1@181.33,124.682 D27.2@181.33,125.428
NetD28_1: D28.1 R568.2 | length 3.2
  Top Layer w0.5: R568.2@171.748,307.368 171.748,305.937 172.345,305.339 D28.1@173.285,305.339
NetD29_1: D29.1 R569.2 | length 3.3
  Top Layer w0.5: R569.2@171.75,216.4 171.75,214.787 172.166,214.371 D29.1@173.287,214.371
NetD30_1: D30.1 R570.2 | length 3.3
  Top Layer w0.5: R570.2@171.75,125.405 171.75,123.853 172.227,123.376 D30.1@173.287,123.376
NetD31_1: D31.1 R318.2 | length 3.4
  Top Layer w0.5: D31.1@193.8,83.876 193.823,83.9 194.6,83.9 195.45,83.05 R318.2@195.45,81.684
NetD32_1: D32.1 R322.2 | length 3.3
  Top Layer w0.5: D32.1@193.798,265.84 194.605,265.84 195.448,264.998 R322.2@195.448,263.648
NetD33_1: D33.1 R323.2 | length 3.4
  Top Layer w0.5: D33.1@193.839,174.874 194.69,174.874 195.489,174.075 R323.2@195.489,172.682
NetFB1_2: FB1.2 R134.1 | length 1.5
  Top Layer w0.203: R134.1@24.456,159.956 FB1.2@25.912,159.956
NetFB2_2: FB2.2 R136.1 | length 1.5
  Top Layer w0.203: R136.1@24.456,163.213 24.466,163.203 FB2.2@25.927,163.203
NetFB4_2: FB4.2 R139.1 | length 1.5
  Top Layer w0.203: R139.1@24.456,127.698 FB4.2@25.912,127.698
NetFB5_2: FB5.2 R141.1 | length 1.5
  Top Layer w0.203: R141.1@24.456,130.955 25.917,130.955 FB5.2@25.927,130.945
NetFB7_2: FB7.2 R144.1 | length 1.5
  Top Layer w0.203: R144.1@24.498,143.771 FB7.2@25.954,143.771
NetFB8_2: FB8.2 R146.1 | length 1.5
  Top Layer w0.203: R146.1@24.498,147.028 25.959,147.028 FB8.2@25.969,147.018
NetJ26_11: J26.11 TP19.1 | length 6.3
  Top Layer w0.203: v2(56.302,286.618) 56.318,286.603 TP19.1@56.318,285.6
  Bottom Layer w0.203: v2(56.302,286.618) 56.302,289.73 56.558,289.985 J26.11@58.402,289.985
NetJ26_12: J26.12 R481.2 | length 8.2
  Top Layer w0.229: R481.2@62.322,283.42 v2(62.322,284.3)
  Bottom Layer w0.229: J26.12@60.402,289.985 61.886,289.985 62.322,289.55 v2(62.322,284.3)
NetJ26_13: J26.13 TP18.1 | length 8.2
  Top Layer w0.203: TP18.1@53.636,285.662 v2(53.636,286.6)
  Bottom Layer w0.203: v2(53.636,286.6) 53.636,287.933 56.488,290.785 J26.13@58.402,290.785
NetJ26_14: J26.14 R478.2 | length 9.5
  Top Layer w0.229: R478.2@63.302,283.42 v2(63.302,284.3)
  Bottom Layer w0.229: J26.14@60.402,290.785 62.001,290.785 63.302,289.484 v2(63.302,284.3)
NetJ26_15: J26.15 TP16.1 | length 10.8
  Top Layer w0.203: TP16.1@51.102,285.6 v2(51.102,286.6)
  Bottom Layer w0.203: v2(51.102,286.6) 51.102,287.4 54.202,290.5 55.602,290.5 56.688,291.585 J26.15@58.402,291.585
NetJ26_16: J26.16 R477.2 | length 27.3
  Top Layer w0.229: R477.2@51.002,277.6 51.002,278.4 55.002,282.4 v2(61.112,282.4)
  Bottom Layer w0.229: J26.16@60.402,291.585 62.017,291.585 64.304,289.298 64.304,282.744 63.96,282.4 v2(61.112,282.4)
NetJ26_18: J26.18 R475.2 | length 12
  Top Layer w0.229: R475.2@65.28,283.42 65.28,284.378 v2(65.302,284.4)
  Bottom Layer w0.229: J26.18@60.402,292.385 62.167,292.385 65.302,289.25 v2(65.302,284.4)
NetJ26_20: J26.20 R471.2 | length 13.4
  Top Layer w0.229: R471.2@66.28,283.42 66.28,284.378 v2(66.302,284.4)
  Bottom Layer w0.229: J26.20@60.402,293.185 62.393,293.185 66.302,289.276 v2(66.302,284.4)
NetJ26_22: J26.22 R469.2 | length 14.7
  Top Layer w0.229: R469.2@67.28,283.42 67.28,284.368 v2(67.312,284.4)
  Bottom Layer w0.229: J26.22@60.402,293.985 62.502,293.985 67.312,289.175 v2(67.312,284.4)
NetJ26_25: J26.25 R467.1 | length 7.3
  Top Layer w0.203: R467.1@51.902,294.716 v2(51.902,295.385)
  Bottom Layer w0.203: v2(51.902,295.385) 52.102,295.585 J26.25@58.402,295.585
NetJ26_45: J26.45 R449.1 | length 5.2
  Top Layer w0.203: R449.1@54.25,302.1 v2(54.25,302.9)
  Bottom Layer w0.203: v2(54.25,302.9) 54.936,303.585 J26.45@58.402,303.585
NetJ26_46: J26.46 R367.2 | length 2.3
  Top Layer w0.229: v2(61.902,303.585) 62.672,303.585 R367.2@62.686,303.6
  Bottom Layer w0.229: J26.46@60.408,303.592 J26.46@60.402,303.585 v2(61.902,303.585)
NetJ26_50: J26.50 R445.2 | length 5.8
  Top Layer w0.203: R445.2@64.602,303.7 v2(64.602,305.185)
  Top Layer w0.229: R445.2@64.602,303.7 R445.2@64.702,303.6
  Bottom Layer w0.203: J26.50@60.402,305.185 v2(64.602,305.185)
NetJ26_64: J26.64 R355.2 | length 7.8
  Top Layer w0.229: v2(63.686,306.3) 63.686,305.6 R355.2@63.702,305.616
  Bottom Layer w0.229: J26.64@60.402,310.785 62.402,310.785 63.702,309.485 63.702,306.316 v2(63.686,306.3)
NetJ26_76: J26.76 R304.2 | length 3.3
  Top Layer w0.203: v2(62.771,318.4) R304.2@63.568,318.4 ; R304.2@63.599,318.297 R304.2@63.602,318.3
  Bottom Layer w0.203: J26.76@60.402,318.785 62.386,318.785 v2(62.771,318.4)
NetJ26_89: J26.89 R411.1 | length 6.3
  Top Layer w0.203: v2(52.902,324.385) R411.1@52.902,325.204
  Bottom Layer w0.203: v2(52.902,324.385) J26.89@58.402,324.385
NetJ26_104: J26.104 R396.2 | length 6.2
  Top Layer w0.25: v2(65.688,330.286) 65.702,330.3 R396.2@65.702,331.092
  Bottom Layer w0.25: J26.104@60.402,329.985 65.387,329.985 v2(65.688,330.286)
NetR21_1: R21.1 U24.3 | length 2.2
  Top Layer w0.254: R21.1@166.4,31.582 166.4,31.927 166.75,32.278 U24.3@166.75,33.6
NetR23_2: R23.2 U62.1 | length 2.2
  Top Layer w0.203: U62.1@145.227,43.555 145.227,44.2 145.792,44.2 146.242,44.65 R23.2@146.242,45
NetR31_1: R31.1 U63.3 | length 2.2
  Top Layer w0.305: R31.1@133.598,31.582 133.949,31.932 U63.3@133.949,33.6
NetR38_1: R38.1 U11.32 | length 3.5
  Top Layer w0.203: R38.1@47.809,165.521 U11.32@51.343,165.521
NetR41_1: R41.1 R42.1 R43.1 R44.2 R45.2 R46.2 | length 12.9
  Top Layer w0.508: R41.1@213.547,3.192 214.734,3.192 ; R43.1@213.547,6.06 214.734,6.06 ; R42.1@213.547,8.928 214.734,8.928 ; R44.2@215.921,3.192 214.734,3.192 ; R46.2@215.921,6.06 214.734,6.06 ; R45.2@215.921,8.928 214.734,8.928 ; 214.734,3.192 214.734,6.06 ; 214.734,6.06 214.734,8.928
NetR44_1: R44.1 R45.1 R46.1 R47.2 R48.2 R49.2 | length 12.8
  Top Layer w0.508: R44.1@218.821,3.192 219.99,3.192 ; R46.1@218.821,6.06 220.006,6.06 ; R45.1@218.821,8.928 220.006,8.928 ; R47.2@221.19,3.192 219.99,3.192 ; R49.2@221.19,6.06 220.006,6.06 ; R48.2@221.19,8.928 220.006,8.928 ; 219.99,3.192 220.006,3.207 220.006,6.06 ; 220.006,6.06 220.006,8.928
NetR51_1: R51.1 R52.1 R53.1 R54.2 R55.2 R56.2 | length 13.1
  Top Layer w0.508: R51.1@229.442,3.192 230.659,3.192 ; R53.1@229.442,6.06 230.582,6.06 ; R52.1@229.442,8.928 230.582,8.928 ; R54.2@231.876,3.192 230.659,3.192 ; R56.2@231.876,6.06 230.582,6.06 ; R55.2@231.876,8.928 230.582,8.928 ; 230.582,6.06 230.582,8.928 ; 230.582,6.06 230.582,3.269 230.659,3.192
NetR54_1: R54.1 R55.1 R56.1 R57.2 R58.2 R59.2 | length 12.7
  Top Layer w0.508: R54.1@234.776,3.192 235.901,3.192 ; R56.1@234.776,6.06 235.934,6.06 ; R55.1@234.776,8.928 235.934,8.928 ; R57.2@237.092,3.192 235.901,3.192 ; R59.2@237.092,6.06 235.934,6.06 ; R58.2@237.092,8.928 235.934,8.928 ; 235.901,3.192 235.934,3.224 235.934,6.06 ; 235.934,6.06 235.934,8.928
NetR76_2: R76.2 U60.1 | length 2.2
  Top Layer w0.203: R76.2@96.68,119 97.9,119 98.15,118.75 U60.1@98.15,118.1
NetR101_1: R101.1 U51.3 | length 2.7
  Top Layer w0.229: U51.3@106.243,300.431 106.243,298.946 106.546,298.643 R101.1@106.546,297.846
NetR102_1: R102.1 U51.6 | length 2.1
  Top Layer w0.229: R102.1@108.193,298.296 U51.6@108.193,300.431
NetR103_1: R103.1 U51.8 | length 1
  Top Layer w0.229: U51.8@108.843,306.331 R103.1@109.846,306.331
NetR105_1: R105.1 U51.11 | length 2.6
  Top Layer w0.229: U51.11@106.841,306.383 U51.11@106.893,306.331 R105.1@106.893,308.893
NetR106_1: R106.1 U52.3 | length 2.7
  Top Layer w0.229: U52.3@95.102,288.013 95.102,286.588 95.406,286.285 R106.1@95.406,285.429
NetR107_1: R107.1 U52.6 | length 2.1
  Top Layer w0.229: R107.1@97.052,285.879 U52.6@97.052,288.013
NetR108_1: R108.1 U52.8 | length 1
  Top Layer w0.229: U52.8@97.702,293.913 R108.1@98.706,293.913
NetR110_1: R110.1 U52.11 | length 2.6
  Top Layer w0.229: U52.11@95.752,293.913 R110.1@95.752,296.476
NetR112_1: R112.1 U53.3 | length 2.1
  Top Layer w0.229: U53.3@79.812,279.273 79.812,278.026 80.115,277.723 R112.1@80.115,277.32
NetR114_1: R114.1 U53.6 | length 2.1
  Top Layer w0.229: R114.1@81.762,277.138 U53.6@81.762,279.273
NetR116_1: R116.1 U53.8 | length 1.2
  Top Layer w0.229: U53.8@82.412,285.173 R116.1@83.601,285.173
NetR129_2: R129.2 U13.2 | length 1.2
  Top Layer w0.203: R129.2@54.107,338.862 U13.2@55.294,338.862
NetR133_1: R133.1 U14.10 | length 2
  Top Layer w0.229: R133.1@8.7,161.6 U14.10@10.691,161.6
NetR135_1: R135.1 U15.10 | length 2
  Top Layer w0.229: R135.1@8.7,129.342 U15.10@10.691,129.342
NetR138_1: R138.1 U16.10 | length 1.8
  Top Layer w0.229: R138.1@8.915,145.415 U16.10@10.733,145.415
NetR168_1: R168.1 U53.11 | length 2.6
  Top Layer w0.229: U53.11@80.462,285.173 R168.1@80.462,287.735
NetR170_1: R170.1 U54.3 | length 1.8
  Top Layer w0.229: U54.3@61.951,275.228 R170.1@63.737,275.228
NetR192_1: R192.1 U54.8 | length 1.4
  Top Layer w0.229: R192.1@54.737,273.928 U54.8@56.151,273.928
NetR209_1: R209.1 U54.5 | length 0.7
  Top Layer w0.229: U54.5@56.151,275.878 R209.1@56.151,276.6
NetR247_2: R247.2 U35.1 | length 2.2
  Top Layer w0.203: U35.1@65.56,102.625 66.175,102.625 66.175,102.08 66.645,101.61 R247.2@67.005,101.61
NetU9_1: U9.1 U9.2 | length 0.7
  Top Layer w0.203: U9.2@77.702,329.468 U9.1@78.352,329.468
OC1_IO: C390.1 J26.21 R470.1 | length 5.3
  Top Layer w0.203: R470.1@54.378,294.865 54.378,294.809 54.402,294.785 C390.1@54.402,293.976 v2(55.402,293.976)
  Bottom Layer w0.203: v2(55.402,293.976) J26.21@58.802,293.976
OC2_IO: C391.1 J26.19 R472.1 | length 5.1
  Top Layer w0.203: R472.1@54.402,292.2 C391.1@54.402,293.091 v2(55.402,293.091)
  Bottom Layer w0.203: v2@55.488,293.176 v2(55.402,293.091) 55.893,293.091 56.002,293.2 58.387,293.2 J26.19@58.402,293.185
OC3_IO: C392.1 J26.17 R476.1 | length 5.3
  Top Layer w0.203: R476.1@54.402,290.409 C392.1@54.402,291.3 v2(55.402,291.3)
  Bottom Layer w0.203: v2(55.402,291.3) 56.488,292.385 J26.17@58.402,292.385
OC_L1: R307.2 R470.2 U41.7 | length 85.5
  Top Layer w0.203: R470.2@55.378,294.865 55.833,294.865 56.688,294.01 56.688,288.815 58.502,287 68.102,287 69.3,285.802 69.3,268.6 v2(67.3,266.6)
  Top Layer w0.229: v2(81.026,255.27) 93.83,255.27 94.827,254.273 R307.2@94.907,254.273 94.907,254.203 97.1,252.01 97.1,251.299 U41.7@97.908,250.491
  Signal Layer 2 w0.203: v2(67.3,266.6) 67.3,258.463 73.026,252.737 v2(73.076,252.737)
  Bottom Layer w0.229: v2(73.076,252.737) 73.076,253.043 75.303,255.27 v2(81.026,255.27)
OC_L2: R339.2 R472.2 U47.7 | length 160.8
  Top Layer w0.203: R472.2@55.402,292.2 55.902,292.2 56.151,291.952 56.151,288.565 58.42,286.296 68.007,286.296 68.8,285.502 68.8,269.084 66.018,266.302 v2(66.018,264.143) ; v2(81.534,233.893) 84.625,230.803 84.625,167.237 88.049,163.813 R339.2@93.725,163.813 95.912,166 96.624,166 U47.7@97.437,166.814
  Bottom Layer w0.203: v2(66.018,264.143) 66.018,254.984 77.87,243.132 77.87,237.545 81.522,233.893 v2(81.534,233.893)
OC_L3: R177.2 R476.2 U21.7 | length 190.3
  Top Layer w0.203: R476.2@55.402,290.409 55.402,288.527 58.43,285.5 67.859,285.5 68.302,285.056 68.302,269.422 64.72,265.84 v2(64.6,265.84) ; v2(81.393,230.69) 82.762,229.322 82.762,229.108 82.762,166.173 89.1,159.835 89.1,139.265 95.794,132.571 R177.2@97.842,132.571 100.071,134.8 100.852,134.8 U21.7@101.624,135.572
  Bottom Layer w0.203: v2(64.6,265.84) 64.6,255.498 77,243.099 77,235.084 v2(81.393,230.69)
OC_TOP_L1: C300.1 R296.1 R298.2 U38.2 | length 10.6
  Top Layer w0.203: U38.2@207.418,258.972 207.418,260.016 207.524,260.122 209.648,260.122 C300.1@209.798,259.972 ; R296.1@209.282,265.416 209.886,265.416 210.664,264.638 R298.2@210.664,260.098 C300.1@209.798,260.098
OH_BOT_L1: R204.1 U25.4 | length 11.4
  Top Layer w0.5: v1(211.07,311.032) U25.4@211.07,312.358
  Top Layer w1: R204.1@215.871,304.6 215.903,304.568 v1(216.996,304.568)
  Signal Layer 2 w0.8: v1(211.07,311.032) 211.07,310.494 v1(216.996,304.568)
OH_BOT_L2: R219.1 U26.4 | length 11.5
  Top Layer w0.5: v1(211.072,220.064) U26.4@211.072,221.39
  Top Layer w1: R219.1@215.766,213.428 R219.1@215.873,213.428 ; R219.1@215.873,213.6 v1(216.998,213.6)
  Signal Layer 2 w0.8: v1(211.072,220.064) 211.072,219.526 v1(216.998,213.6)
OH_BOT_L3: R235.1 U27.4 | length 11.4
  Top Layer w0.5: v1(211.072,129.069) U27.4@211.072,130.394
  Top Layer w1: R235.1@215.873,122.605 v1(216.998,122.605)
  Signal Layer 2 w0.8: v1@211.07,129.064 211.07,128.526 v1@216.996,122.6
OL_BOT_L1: R203.1 U25.6 | length 15
  Top Layer w0.5: v1(213.61,311.032) U25.6@213.61,312.358
  Top Layer w1: R203.1@215.871,301.856 v1(217.116,301.856)
  Signal Layer 2 w0.8: v1(213.61,311.032) 213.61,309.99 218.911,304.689 218.911,303.1 217.667,301.856 v1(217.116,301.856)
OL_BOT_L2: R218.1 U26.6 | length 14.3
  Top Layer w0.5: v1(213.612,220.064) U26.6@213.612,221.39
  Top Layer w1: R218.1@215.873,210.888 v1(217.118,210.888)
  Signal Layer 2 w0.8: v1(213.612,220.064) 213.612,219.028 218.5,214.141 218.5,212.27 v1(217.118,210.888)
OL_BOT_L3: R233.1 U27.6 | length 14.3
  Top Layer w0.5: v1(213.612,129.069) U27.6@213.612,130.394
  Top Layer w1: R233.1@215.873,119.9 215.881,119.892 v1(217.118,119.892)
  Signal Layer 2 w0.8: v1@213.61,129.064 213.61,128.028 218.498,123.141 218.498,121.27 v1@217.116,119.888
OP_IDCM: C275.2 R273.2 R276.2 U8.7 | length 13.1
  Top Layer w0.203: R273.2@81.502,328.467 81.502,325.8 83.202,324.1 85.502,324.1 86.887,322.716 U8.7@86.887,321.554 86.887,320.694 86.614,320.421 C275.2@86.614,320.059 R276.2@86.614,319.086
OP_IDCN: C230.2 R240.1 R244.1 U8.1 | length 13.3
  Top Layer w0.203: R240.1@82.502,328.467 82.502,325.69 83.528,324.664 87.51,324.664 88.157,325.311 U8.1@88.157,326.954 88.157,327.775 87.887,328.045 C230.2@87.887,328.43 R244.1@87.887,329.386
OP_ISN1: C167.1 R310.1 R313.1 U9.7 | length 3.5
  Top Layer w0.203: R310.1@72.759,327.775 72.759,328.169 72.761,328.17 R313.1@72.761,329.56 C167.1@73.676,329.56 ; C167.1@73.676,329.568 C167.1@73.676,329.56 ; U9.7@74.452,329.468 74.36,329.56 C167.1@73.676,329.56
OP_ISN2: C313.1 R347.1 R349.1 U9.8 | length 2.6
  Top Layer w0.203: R347.1@71.868,323.761 C313.1@72.759,323.761 R349.1@73.674,323.761 74.345,323.761 U9.8@74.452,323.868
OP_ISN3: C335.1 R180.1 R184.1 U9.14 | length 2.7
  Top Layer w0.203: U9.14@78.352,323.868 78.49,323.73 R184.1@80.111,323.73 ; R184.1@80.111,323.761 80.122,323.75 R180.1@81.039,323.75
OP_VDC+: C175.2 R24.1 R28.2 U61.1 | length 4.8
  Top Layer w0.203: R28.2@84.27,314.224 C175.2@85.226,314.224 85.511,314.224 85.781,314.494 U61.1@86.702,314.494 86.702,315.254 ; R24.1@85.226,315.275 86.682,315.275
OP_VDCM: C455.2 R33.1 R37.2 U61.7 | length 9.2
  Top Layer w0.203: R33.1@89.002,309.189 89.618,309.189 89.902,309.473 89.902,312.649 90.477,313.224 U61.7@92.102,313.224 92.967,313.224 93.229,312.962 C455.2@93.597,312.962 ; C455.2@93.602,312.967 C455.2@93.597,312.962 ; R37.2@94.57,312.964 94.568,312.962 C455.2@93.597,312.962
OUTH_MID_L1: R258.1 U32.6 | length 10.2
  Top Layer w0.5: v1(190.185,310.251) 190.195,310.26 U32.6@190.195,311.668
  Top Layer w1: R258.1@192.943,303.23 v1(192.943,305.003)
  Signal Layer 2 w0.8: v1(190.185,310.251) 190.185,306.788 191.97,305.003 v1(192.943,305.003)
OUTH_MID_L2: R262.1 U33.6 | length 10.2
  Top Layer w0.5: v1(190.187,219.282) 190.197,219.292 U33.6@190.197,220.7
  Top Layer w1: R262.1@192.945,212.207 v1(192.945,214.035)
  Signal Layer 2 w0.8: v1(190.187,219.282) 190.187,215.819 191.972,214.035 v1(192.945,214.035)
OUTH_MID_L3: R266.1 U34.6 | length 10.2
  Top Layer w0.5: v1(190.187,128.287) 190.197,128.297 U34.6@190.197,129.705
  Top Layer w1: R266.1@192.89,121.266 192.945,121.321 v1(192.945,123.039)
  Signal Layer 2 w0.8: v1(190.187,128.287) 190.187,124.824 191.972,123.039 v1(192.945,123.039)
OUTH_MID_SN_L1: R303.1 U39.6 | length 8.6
  Top Layer w0.5: U39.6@177.389,259.568 177.389,261.042 v1(177.398,261.05)
  Top Layer w1: v1(177.128,266.272) R303.1@177.128,268.1
  Signal Layer 2 w0.8: v1(177.128,266.272) 177.128,265.593 177.4,265.321 v1(177.398,261.05)
OUTH_MID_SN_L2: R341.1 U46.6 | length 8.6
  Top Layer w0.5: U46.6@177.439,168.61 v1@177.439,170.084
  Top Layer w1: v1(177.17,175.306) R341.1@177.17,177.134
  Signal Layer 2 w0.8: v1(177.17,175.306) 177.17,174.627 177.442,174.355 v1(177.439,170.084)
OUTH_MID_SN_L3: R172.1 U20.6 | length 8.6
  Top Layer w0.5: U20.6@177.391,77.604 v1@177.391,79.078
  Top Layer w1: v1(177.13,84.308) R172.1@177.13,86.136
  Signal Layer 2 w0.8: v1(177.13,84.308) 177.13,83.63 177.402,83.358 v1(177.4,79.087)
OUTH_TOP_L1: R295.1 U38.4 | length 11.8
  Top Layer w0.5: U38.4@204.878,258.972 v1(204.878,260.298)
  Top Layer w1: v1(198.832,266.934) R295.1@200.184,266.934
  Signal Layer 2 w0.8: 198.83,266.346 v1(204.878,260.298) ; 198.832,266.346 v1(198.832,266.934)
OUTH_TOP_L2: R334.1 U45.4 | length 11.7
  Top Layer w0.5: U45.4@204.919,168.006 v1(204.919,169.332)
  Top Layer w1.2: v1(198.874,175.968) R334.1@200.119,175.968
  Signal Layer 2 w0.8: v1(198.874,175.968) 198.874,175.377 v1(204.919,169.332)
OUTH_TOP_L3: R165.1 U19.4 | length 11.7
  Top Layer w0.5: U19.4@204.88,77.011 v1(204.88,78.334)
  Top Layer w1: v1(198.834,84.97) R165.1@200.079,84.97
  Signal Layer 2 w0.8: v1(198.834,84.97) 198.834,84.38 v1(204.88,78.334)
OUTL_TOP_L1: R294.1 U38.6 | length 14.5
  Top Layer w0.5: U38.6@202.338,258.972 v1(202.338,260.298)
  Top Layer w1: v1(198.832,269.474) R294.1@200.077,269.474
  Signal Layer 2 w0.8: 197.298,265.667 202.278,260.686 202.278,260.357 v1(202.338,260.298) ; 197.3,265.667 197.3,267.942 v1(198.832,269.474)
OUTL_TOP_L2: R333.1 U45.6 | length 14.4
  Top Layer w0.5: U45.6@202.379,168.006 v1(202.379,169.332)
  Top Layer w1.2: v1@198.874,178.508 R333.1@200.119,178.508
  Signal Layer 2 w0.8: v1@198.874,178.508 197.372,177.006 197.372,174.728 202.379,169.721 v1(202.379,169.332)
  other v1: 198.897,178.508
OUTL_TOP_L3: R164.1 U19.6 | length 14.4
  Top Layer w0.5: U19.6@202.34,77.011 v1(202.34,78.334)
  Top Layer w1: v1(198.834,87.51) R164.1@200.079,87.51
  Signal Layer 2 w0.8: v1(198.834,87.51) 197.4,86.076 197.4,83.659 202.34,78.719 v1(202.34,78.334)
PCC_L1: F1.2 J14.1 TP21.1
  other v1: 25.548,3.416 27.548,3.416 29.548,3.416 31.548,3.416 33.548,3.416 26.548,5.416 28.548,5.416 30.548,5.416 32.548,5.416 34.548,5.416 25.548,7.416 27.548,7.416 29.548,7.416 31.548,7.416 33.548,7.416 16.548,9.416 18.548,9.416 20.548,9.416 22.548,9.416 24.548,9.416 26.548,9.416 28.548,9.416 30.548,9.416 32.548,9.416 34.548,9.416 17.548,11.416 19.548,11.416 21.548,11.416 23.548,11.416 25.548,11.416 27.548,11.416 29.548,11.416 31.548,11.416 33.548,11.416 16.548,13.416 18.548,13.416 20.548,13.416 22.548,13.416 24.548,13.416 26.548,13.416 28.548,13.416 30.548,13.416 32.548,13.416 34.548,13.416 17.548,15.416 19.548,15.416 21.548,15.416 23.548,15.416 29.548,15.416 31.548,15.416 33.548,15.416 16.548,17.416 18.548,17.416 20.548,17.416 22.548,17.416 30.548,17.416 32.548,17.416 34.548,17.416 17.548,19.416 19.548,19.416 21.548,19.416 23.548,19.416 25.548,19.416 27.548,19.416 16.548,21.416 18.548,21.416 20.548,21.416 22.548,21.416 24.548,21.416 26.548,21.416 17.548,23.416 19.548,23.416 21.548,23.416 23.548,23.416 25.548,23.416
  other v2: 15.5,3.416 16.9,3.416 18.3,3.416 19.7,3.416 21.1,3.416 22.5,3.416 15.5,5 22.5,5 15.5,6.5 16.9,6.5 18.3,6.5 19.7,6.5 21.1,6.5 22.5,6.5 30.41,20.5 31.41,20.5 32.41,20.5 33.41,20.5 29.41,21.5 34.41,21.5 29.41,22.5 34.41,22.5 29.41,23.5 34.41,23.5 29.41,24.5 34.41,24.5 30.41,25.5 31.41,25.5 32.41,25.5 33.41,25.5
PCC_L2: F2.2 J16.1 TP25.1
  other v1: 51.548,3.416 53.548,3.416 55.548,3.416 57.548,3.416 59.548,3.416 52.548,5.416 54.548,5.416 56.548,5.416 58.548,5.416 60.548,5.416 51.548,7.416 53.548,7.416 55.548,7.416 57.548,7.416 59.548,7.416 42.548,9.416 44.548,9.416 46.548,9.416 48.548,9.416 50.548,9.416 52.548,9.416 54.548,9.416 56.548,9.416 58.548,9.416 60.548,9.416 43.548,11.416 45.548,11.416 47.548,11.416 49.548,11.416 51.548,11.416 53.548,11.416 55.548,11.416 57.548,11.416 59.548,11.416 42.548,13.416 44.548,13.416 46.548,13.416 48.548,13.416 50.548,13.416 52.548,13.416 54.548,13.416 56.548,13.416 58.548,13.416 60.548,13.416 43.548,15.416 45.548,15.416 47.548,15.416 49.548,15.416 55.548,15.416 57.548,15.416 59.548,15.416 42.548,17.416 44.548,17.416 46.548,17.416 48.548,17.416 56.548,17.416 58.548,17.416 43.548,19.416 45.548,19.416 47.548,19.416 49.548,19.416 51.548,19.416 53.548,19.416 42.548,21.416 44.548,21.416 46.548,21.416 48.548,21.416 50.548,21.416 52.548,21.416 43.548,23.416 45.548,23.416 47.548,23.416 49.548,23.416 51.548,23.416
  other v2: 41.504,3.416 43.025,3.416 44.406,3.416 45.786,3.416 47.167,3.416 48.548,3.416 41.504,5 48.548,5 41.504,6.502 42.903,6.502 44.302,6.502 45.702,6.502 47.101,6.502 48.548,6.502 56.292,20.5 57.292,20.5 58.292,20.5 59.292,20.5 55.292,21.5 60.292,21.5 55.292,22.5 60.292,22.5 55.292,23.5 60.292,23.5 55.292,24.5 60.292,24.5 56.292,25.5 57.292,25.5 58.292,25.5 59.292,25.5
PCC_L3: F3.2 J17.1 TP27.1
  other v1: 79.548,3.416 81.548,3.416 83.548,3.416 85.548,3.416 78.548,5.416 80.548,5.416 82.548,5.416 84.548,5.416 77.548,7.416 79.548,7.416 81.548,7.416 83.548,7.416 85.548,7.416 68.548,9.416 70.548,9.416 72.548,9.416 74.548,9.416 76.548,9.416 78.548,9.416 80.548,9.416 82.548,9.416 84.548,9.416 67.548,11.416 69.548,11.416 71.548,11.416 73.548,11.416 75.548,11.416 77.548,11.416 79.548,11.416 81.548,11.416 83.548,11.416 85.548,11.416 68.548,13.416 70.548,13.416 72.548,13.416 74.548,13.416 76.548,13.416 78.548,13.416 80.548,13.416 82.548,13.416 84.548,13.416 67.548,15.416 69.548,15.416 71.548,15.416 73.548,15.416 75.548,15.416 81.548,15.416 83.548,15.416 85.548,15.416 68.548,17.416 70.548,17.416 72.548,17.416 74.548,17.416 82.548,17.416 84.548,17.416 67.548,19.416 69.548,19.416 71.548,19.416 73.548,19.416 75.548,19.416 77.548,19.416 79.548,19.416 68.548,21.416 70.548,21.416 72.548,21.416 74.548,21.416 76.548,21.416 78.548,21.416 67.548,23.416 69.548,23.416 71.548,23.416 73.548,23.416 75.548,23.416 77.548,23.416
  other v2: 67,3.416 68.405,3.416 69.811,3.416 71.216,3.416 72.621,3.416 74.026,3.416 67,5 74.026,5 67,6.5 68.405,6.5 69.811,6.5 71.216,6.5 72.621,6.5 74.026,6.5 82,20.5 83,20.5 84,20.5 85,20.5 81,21.5 86,21.5 81,22.5 86,22.5 81,23.5 86,23.5 81,24.5 86,24.5 82,25.5 83,25.5 84,25.5 85,25.5
PIN25_AIN: C486.1 J26.96 S2.1 | length 8.9
  Top Layer w0.203: v2(61.902,326.799) C486.1@63.227,326.8 ; C486.1@63.227,326.8 63.227,327.173 63.602,327.548 64.346,327.548 66.322,329.525 S2.1@67.902,329.525
  Bottom Layer w0.203: J26.96@60.402,326.785 61.888,326.785 v2(61.902,326.799)
PIN27_AIN: C488.1 J26.94 S2.3 | length 7.5
  Top Layer w0.203: v2(65.058,325.985) 65.073,326 C488.1@65.902,326 67.877,326 S2.3@67.902,326.025
  Bottom Layer w0.203: J26.94@60.402,325.985 v2(65.058,325.985)
PIN34_AIN: C485.1 J26.87 S1.1 | length 25.1
  Top Layer w0.203: v2(55.202,323.6) 54.417,323.6 54.402,323.585 C485.1@54.402,323.7 54.402,324.051 54.651,324.3 57.37,324.3 62.138,319.532 71.67,319.532 72.102,319.1 S1.1@72.102,318.4
  Bottom Layer w0.203: v2(55.202,323.6) 58.387,323.6 J26.87@58.402,323.585
PIN36_AIN: C487.1 J26.85 S1.3 | length 23.5
  Top Layer w0.203: v2(56.739,322.785) C487.1@56.002,322.785 56.002,323.242 56.16,323.4 57.03,323.4 61.33,319.1 69.617,319.1 72.052,316.665 72.052,314.95 S1.3@72.102,314.9
  Bottom Layer w0.203: v2(56.739,322.785) J26.85@58.402,322.785
PIN40_AIN: C490.1 J26.81 S3.1 S4.3 | length 37.1
  Top Layer w0.203: v2(55.202,320.7) C490.1@54.402,320.7 54.402,317.752 55.354,316.8 62.703,316.8 62.992,317.089 68.846,317.089 69.392,316.543 69.392,314.583 70.647,313.328 74.95,313.328 75.554,313.932 76.145,313.932 76.848,314.635 S4.3@77.901,314.635 S3.1@77.901,311.9
  Bottom Layer w0.203: v2(55.202,320.7) 55.902,320.7 56.388,321.185 J26.81@58.402,321.185
PIN42_AIN: C489.1 J26.79 S4.1 | length 33
  Top Layer w0.203: C489.1@56.447,319.827 C489.1@56.474,319.8 ; v2(57.202,320.099) 56.552,320.099 C489.1@56.452,320 56.142,320 55.728,319.585 55.728,317.646 56.127,317.246 61.796,317.246 62.171,317.621 69.135,317.621 70.106,316.65 70.106,314.672 70.967,313.811 74.46,313.811 75.169,314.52 75.923,314.52 77.901,316.499 S4.1@77.901,318.135
  Bottom Layer w0.203: v2(57.202,320.099) 57.202,320.128 57.459,320.385 J26.79@58.402,320.385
